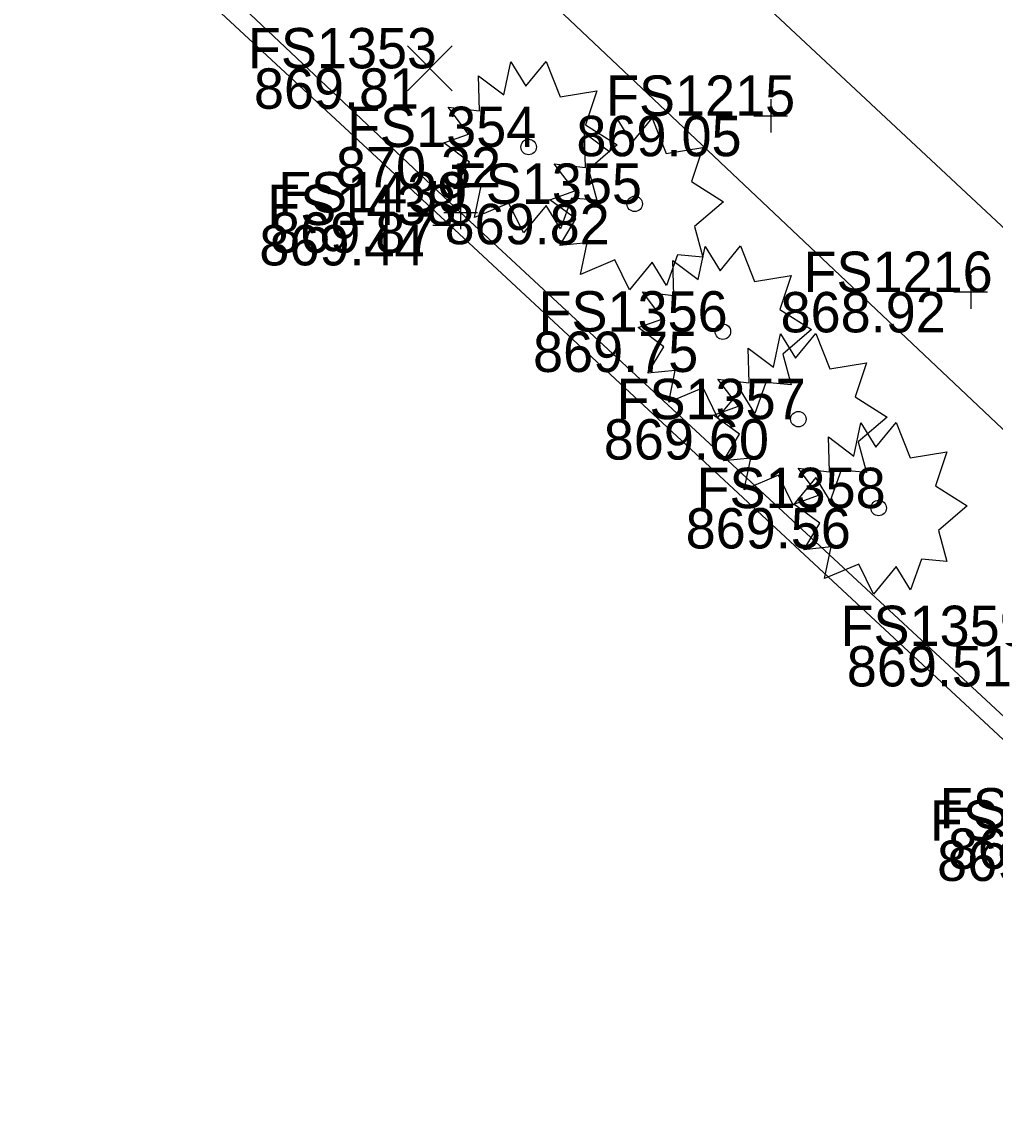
# Model space of a CAD drawing. Extents: x 1479420 to 1479833, y 379731 to 380103.
# Drawn here: x 1479642.79 to 1479671.72, y 379820.46 to 379852.72 of the extents above; entities that cross this region are included whole.
import ezdxf

# ---------------------------------------------------------------- set-up
doc = ezdxf.new("R2010")
doc.units = 0
for name, color, linetype in [('PV_X_Curb', 7, 'Continuous'), ('PV_X_Walk', 7, 'Continuous'), ('SV_X_Random_Point', 7, 'Continuous'), ('SV_X_Shot_Marker', 7, 'Continuous'), ('SV_X_Text_Elevation', 7, 'Continuous'), ('SV_X_Text_Name', 7, 'Continuous'), ('VG_X_Cells', 7, 'Continuous')]:
    doc.layers.add(name, color=color, linetype=linetype)

msp = doc.modelspace()

# ---------------------------------------------------------------- linework, layer by layer
at = {"layer": 'PV_X_Curb'}
for points in [[(1479752.341, 379756.82), (1479734.895, 379773.493), (1479717.229, 379789.662), (1479699.298, 379806.401), (1479688.16, 379794.934), (1479685.526, 379793.897), (1479682.733, 379795.157), (1479681.263, 379797.549), (1479682.493, 379800.746), (1479693.462, 379811.911), (1479675.554, 379828.75), (1479655.832, 379847.057), (1479640.191, 379861.808), (1479628.558, 379849), (1479624.614, 379847.663), (1479622.46, 379848.585), (1479618.996, 379850.857), (1479611.825, 379854.437), (1479601.319, 379856.891), (1479590.521, 379858.038)], [(1479751.933, 379756.628), (1479734.447, 379772.976), (1479716.701, 379789.463), (1479699.4, 379805.742), (1479688.561, 379794.786), (1479685.717, 379793.294), (1479682.291, 379794.8), (1479680.73, 379797.254), (1479682.169, 379801.189), (1479692.652, 379811.907), (1479675.183, 379828.391), (1479655.51, 379846.682), (1479640.151, 379860.926), (1479629.134, 379848.869), (1479624.571, 379847.215), (1479622.228, 379847.911), (1479618.757, 379850.398), (1479611.519, 379853.97), (1479601.347, 379856.369), (1479590.364, 379857.442)]]:
    msp.add_lwpolyline(points, dxfattribs=at)
at = {"layer": 'PV_X_Walk'}
for points in [[(1479685.769, 379833.708), (1479660.411, 379857.395), (1479657.292, 379860.626), (1479660.086, 379863.591), (1479659.321, 379864.377), (1479657.858, 379865.693), (1479656.248, 379867.188), (1479655.369, 379867.881), (1479654.27, 379866.26), (1479652.631, 379864.541), (1479652.351, 379864.607), (1479645.059, 379871.585), (1479642.188, 379874.12), (1479639.084, 379877.042), (1479636.766, 379877.319), (1479635.406, 379877.451), (1479631.457, 379877.614), (1479630.424, 379877.567), (1479629.778, 379877.526), (1479625.011, 379876.78), (1479605.984, 379871.904), (1479600.533, 379870.638), (1479580.734, 379865.6)], [(1479682.443, 379830.686), (1479657.296, 379854.468), (1479652, 379859.64), (1479649.772, 379861.738), (1479651.803, 379859.818), (1479649.833, 379861.569), (1479642.24, 379868.777), (1479639.038, 379871.891), (1479636.885, 379872.56), (1479634.381, 379872.968), (1479631.754, 379873.281), (1479630.076, 379873.213), (1479625.848, 379872.765), (1479606.823, 379868.193), (1479601.313, 379866.859), (1479581.547, 379861.918)]]:
    msp.add_lwpolyline(points, dxfattribs=at)
at = {"layer": 'SV_X_Random_Point'}
for p, q in [((1479654.25, 379850.669), (1479655.584, 379852.004)), ((1479654.25, 379852.004), (1479655.584, 379850.669))]:
    msp.add_line(p, q, dxfattribs=at)
at = {"layer": 'SV_X_Shot_Marker'}
for p, q in [((1479665.044, 379850.427), (1479665.044, 379849.427)), ((1479664.544, 379849.927), (1479665.544, 379849.927)), ((1479665.044, 379849.927), (1479665.044, 379849.927)), ((1479655.832, 379847.557), (1479655.832, 379846.557)), ((1479655.51, 379847.182), (1479655.51, 379846.182)), ((1479655.332, 379847.057), (1479656.332, 379847.057)), ((1479655.832, 379847.057), (1479655.832, 379847.057)), ((1479655.01, 379846.682), (1479656.01, 379846.682)), ((1479655.51, 379846.682), (1479655.51, 379846.682)), ((1479670.987, 379845.192), (1479670.987, 379844.192)), ((1479670.487, 379844.692), (1479671.487, 379844.692)), ((1479670.987, 379844.692), (1479670.987, 379844.692))]:
    msp.add_line(p, q, dxfattribs=at)
at = {"layer": 'VG_X_Cells'}
for points in [[(1479657.768, 379850.81), (1479658.373, 379851.545), (1479658.788, 379850.492), (1479659.88, 379850.672), (1479659.541, 379849.66), (1479660.486, 379849.065), (1479659.63, 379848.33), (1479659.88, 379847.417), (1479659.126, 379847.485), (1479658.801, 379846.572), (1479658.373, 379847.263), (1479657.695, 379846.447), (1479657.266, 379847.333), (1479656.246, 379846.903), (1479656.438, 379847.845), (1479655.626, 379847.762), (1479656.1, 379848.552), (1479655.331, 379849.12), (1479656.07, 379849.383), (1479655.463, 379850.187), (1479656.395, 379850.077), (1479656.365, 379851.115), (1479657.118, 379850.547), (1479657.325, 379851.532), (1479657.768, 379850.81)], [(1479660.919, 379849.121), (1479661.524, 379849.856), (1479661.939, 379848.803), (1479663.031, 379848.983), (1479662.692, 379847.971), (1479663.637, 379847.376), (1479662.781, 379846.641), (1479663.031, 379845.728), (1479662.277, 379845.796), (1479661.952, 379844.883), (1479661.524, 379845.574), (1479660.846, 379844.758), (1479660.417, 379845.644), (1479659.397, 379845.214), (1479659.589, 379846.156), (1479658.777, 379846.073), (1479659.251, 379846.863), (1479658.482, 379847.431), (1479659.221, 379847.694), (1479658.614, 379848.498), (1479659.546, 379848.388), (1479659.516, 379849.426), (1479660.269, 379848.858), (1479660.476, 379849.843), (1479660.919, 379849.121)], [(1479663.539, 379845.325), (1479664.144, 379846.06), (1479664.559, 379845.006), (1479665.651, 379845.186), (1479665.312, 379844.175), (1479666.257, 379843.58), (1479665.401, 379842.845), (1479665.651, 379841.931), (1479664.897, 379842), (1479664.572, 379841.086), (1479664.144, 379841.778), (1479663.466, 379840.961), (1479663.037, 379841.848), (1479662.017, 379841.418), (1479662.209, 379842.36), (1479661.397, 379842.276), (1479661.871, 379843.066), (1479661.102, 379843.635), (1479661.841, 379843.898), (1479661.234, 379844.701), (1479662.166, 379844.591), (1479662.136, 379845.63), (1479662.889, 379845.061), (1479663.096, 379846.046), (1479663.539, 379845.325)], [(1479665.782, 379842.722), (1479666.387, 379843.457), (1479666.802, 379842.404), (1479667.894, 379842.584), (1479667.555, 379841.572), (1479668.5, 379840.977), (1479667.644, 379840.242), (1479667.894, 379839.329), (1479667.14, 379839.397), (1479666.815, 379838.484), (1479666.387, 379839.176), (1479665.709, 379838.359), (1479665.28, 379839.246), (1479664.26, 379838.816), (1479664.452, 379839.757), (1479663.64, 379839.674), (1479664.114, 379840.464), (1479663.345, 379841.032), (1479664.084, 379841.296), (1479663.477, 379842.099), (1479664.409, 379841.989), (1479664.379, 379843.027), (1479665.132, 379842.459), (1479665.339, 379843.444), (1479665.782, 379842.722)], [(1479668.167, 379840.08), (1479668.772, 379840.815), (1479669.187, 379839.762), (1479670.279, 379839.942), (1479669.94, 379838.93), (1479670.885, 379838.335), (1479670.029, 379837.6), (1479670.279, 379836.687), (1479669.525, 379836.755), (1479669.2, 379835.842), (1479668.772, 379836.534), (1479668.094, 379835.717), (1479667.665, 379836.604), (1479666.645, 379836.174), (1479666.837, 379837.115), (1479666.025, 379837.032), (1479666.499, 379837.822), (1479665.73, 379838.39), (1479666.469, 379838.654), (1479665.862, 379839.457), (1479666.794, 379839.347), (1479666.764, 379840.385), (1479667.517, 379839.817), (1479667.724, 379840.802), (1479668.167, 379840.08)]]:
    msp.add_lwpolyline(points, dxfattribs=at)
for centre in [(1479657.852, 379849), (1479661.003, 379847.311), (1479663.623, 379843.515), (1479665.866, 379840.913), (1479668.251, 379838.271)]:
    msp.add_circle(centre, 0.23, dxfattribs=at)

# ---------------------------------------------------------------- texts
at = {"layer": 'SV_X_Text_Elevation'}
for s, p in [('869.81', (1479649.691, 379850.137)), ('869.05', (1479659.271, 379848.727)), ('870.32', (1479652.127, 379847.8)), ('869.82', (1479655.354, 379846.111)), ('869.87', (1479650.173, 379845.857)), ('869.44', (1479649.851, 379845.482)), ('868.92', (1479665.337, 379843.492)), ('869.75', (1479657.983, 379842.315)), ('869.60', (1479660.085, 379839.712)), ('869.56', (1479662.517, 379837.07)), ('869.51', (1479667.305, 379832.971)), ('869.61', (1479670.309, 379827.55)), ('869.18', (1479669.987, 379827.191))]:
    msp.add_text(s, height=1.2, dxfattribs=at).set_placement(p)
at = {"layer": 'SV_X_Text_Name'}
for s, p in [('FS1353', (1479649.513, 379851.337)), ('FS1215', (1479660.151, 379849.927)), ('FS1354', (1479652.459, 379849)), ('FS1355', (1479655.6, 379847.311)), ('FS1439', (1479650.409, 379847.057)), ('FS1438', (1479650.087, 379846.682)), ('FS1216', (1479666.019, 379844.692)), ('FS1356', (1479658.145, 379843.515)), ('FS1357', (1479660.463, 379840.912)), ('FS1358', (1479662.839, 379838.27)), ('FS1359', (1479667.118, 379834.171)), ('FS1436', (1479670.065, 379828.75)), ('FS1437', (1479669.77, 379828.391))]:
    msp.add_text(s, height=1.2, dxfattribs=at).set_placement(p)

doc.saveas('drawing.dxf')
